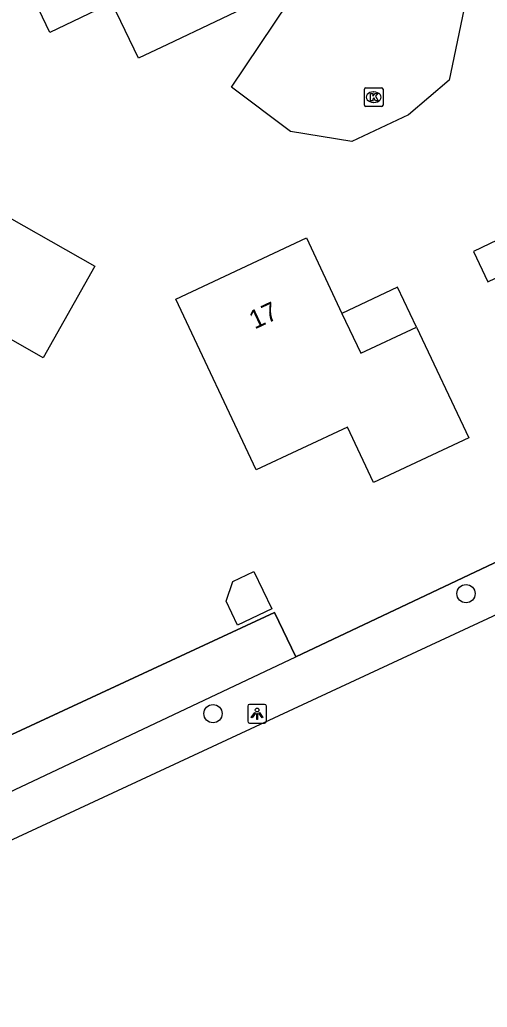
# Model space of a CAD drawing. Extents: x 163268 to 164360, y 381529 to 382285.
# Drawn here: x 163608.7 to 163633.8, y 381585.3 to 381638.4 of the extents above; entities that cross this region are included whole.
import ezdxf

# ---------------------------------------------------------------- set-up
doc = ezdxf.new("R2010")
doc.units = 0
for name, color, linetype in [('IMGEO_Boom', 7, 'Continuous'), ('IMGEO_Fietspad_gesloten', 7, 'Continuous'), ('IMGEO_Groenvoorziening', 7, 'Continuous'), ('IMGEO_Hek', 7, 'Continuous'), ('IMGEO_Kolk', 7, 'Continuous'), ('IMGEO_Lichtpunt', 7, 'Continuous'), ('IMGEO_Pand', 7, 'Continuous'), ('IMGEO_Pand_nummerreeks', 7, 'Continuous'), ('IMGEO_Pand_overbouw', 7, 'Continuous'), ('IMGEO_Rijbaan_lokaal_open', 7, 'Continuous')]:
    doc.layers.add(name, color=color, linetype=linetype)

msp = doc.modelspace()

# ---------------------------------------------------------------- linework, layer by layer
at = {"layer": 'IMGEO_Boom'}
for centre in [(163632.626, 381607.552), (163619.054, 381601.111)]:
    msp.add_circle(centre, 0.489, dxfattribs=at)
at = {"layer": 'IMGEO_Fietspad_gesloten'}
msp.add_lwpolyline([(163694.284, 381634.354), (163682.934, 381629.066), (163588.96, 381585.345)], dxfattribs=at)
at = {"layer": 'IMGEO_Groenvoorziening'}
for points in [[(163623.496, 381604.168), (163677.889, 381629.916), (163692.948, 381637.102)], [(163593.379, 381593.084), (163622.355, 381606.539), (163623.496, 381604.168)], [(163593.379, 381593.084), (163594.654, 381590.515), (163623.496, 381604.168)]]:
    msp.add_lwpolyline(points, dxfattribs=at)
at = {"layer": 'IMGEO_Hek'}
msp.add_lwpolyline([(163677.889, 381629.916), (163623.496, 381604.168), (163622.355, 381606.539), (163589.374, 381591.224), (163586.783, 381590.674)], dxfattribs=at)
at = {"layer": 'IMGEO_Kolk'}
for p, q in [((163627.175, 381633.784), (163627.175, 381634.636)), ((163627.25, 381634.71), (163628.102, 381634.71)), ((163627.663, 381634.49), (163627.688, 381634.49)), ((163628.176, 381634.636), (163628.176, 381633.784)), ((163627.686, 381633.93), (163627.661, 381633.93)), ((163628.102, 381633.71), (163627.25, 381633.71))]:
    msp.add_line(p, q, dxfattribs=at)
for points in [[(163627.175, 381633.784), (163627.175, 381634.636)], [(163627.25, 381634.71), (163628.102, 381634.71)], [(163627.496, 381634.41), (163627.619, 381634.41), (163627.619, 381634.259), (163627.749, 381634.41), (163627.913, 381634.41), (163627.767, 381634.259), (163627.92, 381634.01), (163627.768, 381634.01), (163627.683, 381634.174), (163627.619, 381634.107), (163627.619, 381634.01), (163627.496, 381634.01), (163627.496, 381634.41)], [(163628.176, 381634.636), (163628.176, 381633.784)], [(163628.102, 381633.71), (163627.25, 381633.71)]]:
    msp.add_lwpolyline(points, dxfattribs=at)
for centre, start, end in [((163627.252, 381634.634), 91.552, 178.448), ((163627.252, 381634.634), 91.552, 178.448), ((163628.1, 381634.634), 1.552, 88.448), ((163628.1, 381634.634), 1.552, 88.448), ((163627.252, 381633.786), 181.552, 268.448), ((163627.252, 381633.786), 181.552, 268.448), ((163628.1, 381633.786), 271.552, 358.448), ((163628.1, 381633.786), 271.552, 358.448)]:
    msp.add_arc(centre, 0.0765, start, end, dxfattribs=at)
for centre, major_axis, ratio, start_param, end_param in [((163627.662, 381634.21), (-0.387, 0.002), 0.722429, 4.712389, 7.853982), ((163627.687, 381634.21), (-0.39, 0.002), 0.717154, 1.570796, 4.712389)]:
    msp.add_ellipse(centre, major_axis=major_axis, ratio=ratio, start_param=start_param, end_param=end_param, dxfattribs=at)
at = {"layer": 'IMGEO_Lichtpunt'}
for p, q in [((163620.921, 381601.507), (163620.921, 381600.7)), ((163620.921, 381601.507), (163620.921, 381600.7)), ((163621.823, 381601.602), (163621.015, 381601.602)), ((163621.823, 381601.602), (163621.015, 381601.602)), ((163621.917, 381600.7), (163621.917, 381601.507)), ((163621.917, 381600.7), (163621.917, 381601.507)), ((163621.015, 381600.606), (163621.823, 381600.606)), ((163621.015, 381600.606), (163621.823, 381600.606))]:
    msp.add_line(p, q, dxfattribs=at)
for points in [[(163621.295, 381601.171), (163621.334, 381601.143), (163621.146, 381600.881), (163621.108, 381600.908), (163621.295, 381601.171)], [(163621.397, 381601.123), (163621.444, 381601.123), (163621.444, 381600.801), (163621.397, 381600.801), (163621.397, 381601.123)], [(163621.507, 381601.143), (163621.545, 381601.17), (163621.732, 381600.908), (163621.693, 381600.88), (163621.507, 381601.143)]]:
    msp.add_lwpolyline(points, dxfattribs=at)
msp.add_circle((163621.42, 381601.305), 0.0994, dxfattribs=at)
for centre, start, end in [((163621.015, 381601.507), 90, 180), ((163621.015, 381601.507), 90, 180), ((163621.823, 381601.507), 0, 90), ((163621.823, 381601.507), 0, 90), ((163621.015, 381600.7), 180, 270), ((163621.015, 381600.7), 180, 270), ((163621.823, 381600.7), 270, 0), ((163621.823, 381600.7), 270, 360)]:
    msp.add_arc(centre, 0.0946, start, end, dxfattribs=at)
at = {"layer": 'IMGEO_Pand'}
for points in [[(163614.864, 381646.176), (163615.843, 381644.129), (163618.833, 381645.559), (163621.734, 381639.492), (163616.62, 381637.047), (163615.051, 381636.297), (163613.625, 381639.279), (163610.298, 381637.689), (163605.91, 381646.869), (163612.915, 381650.25), (163614.864, 381646.176)], [(163609.944, 381620.221), (163607.086, 381621.84), (163604.418, 381617.132), (163595.599, 381622.127), (163599.389, 381628.882), (163603.274, 381626.682), (163604.893, 381625.765), (163606.523, 381628.642), (163612.724, 381625.131), (163609.944, 381620.221)], [(163632.771, 381615.911), (163627.665, 381613.512), (163626.263, 381616.493), (163621.365, 381614.192), (163617.055, 381623.363), (163624.067, 381626.658), (163625.973, 381622.6), (163626.978, 381620.459), (163629.963, 381621.862), (163632.771, 381615.911)], [(163622.204, 381606.74), (163620.362, 381605.865), (163619.754, 381607.145), (163620.113, 381608.21), (163621.249, 381608.749), (163622.204, 381606.74)]]:
    msp.add_lwpolyline(points, dxfattribs=at)
at = {"layer": 'IMGEO_Pand_overbouw'}
for points in [[(163636.05, 381627.37), (163633.024, 381625.916), (163633.799, 381624.303), (163636.83, 381625.741)], [(163628.954, 381624.001), (163625.973, 381622.6), (163626.978, 381620.459), (163629.963, 381621.862)]]:
    msp.add_lwpolyline(points, close=True, dxfattribs=at)
at = {"layer": 'IMGEO_Rijbaan_lokaal_open'}
msp.add_lwpolyline([(163620.155, 381656.837), (163627.113, 381642.174), (163632.779, 381640.204), (163631.718, 381635.122), (163629.543, 381633.257), (163626.498, 381631.83), (163623.217, 381632.374), (163620.04, 381634.754), (163623.848, 381640.445), (163616.821, 381655.083)], dxfattribs=at)

# ---------------------------------------------------------------- texts
at = {"layer": 'IMGEO_Pand_nummerreeks'}
msp.add_text('17', height=1, rotation=25.17, dxfattribs=at).set_placement((163621.289, 381621.73))

doc.saveas('drawing.dxf')
